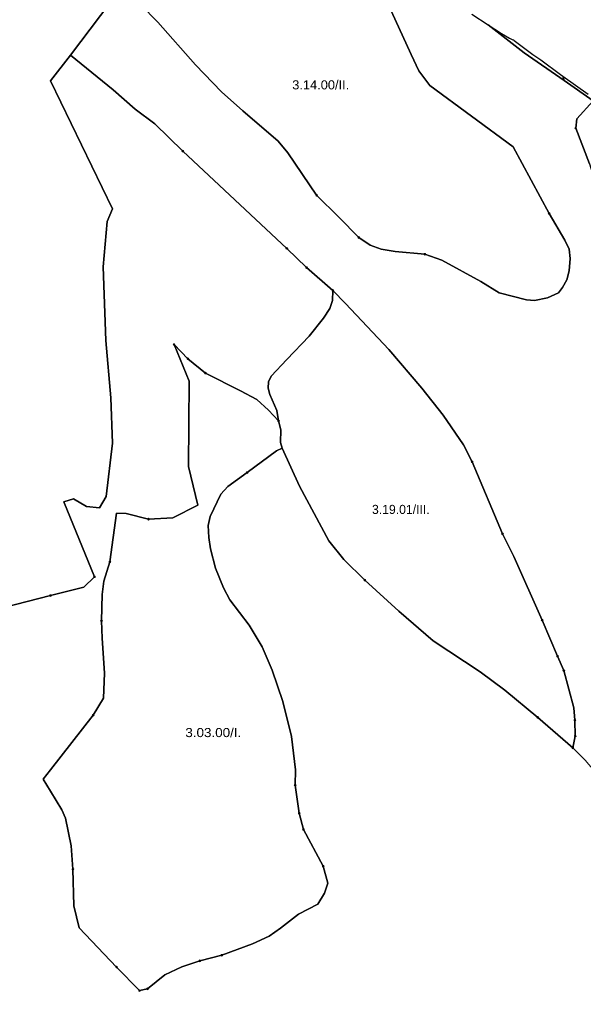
# Model space of a CAD drawing. Extents: x -650455 to -642254, y -1075222 to -1066610.
# Drawn here: x -645034 to -644416, y -1073102 to -1072036 of the extents above; entities that cross this region are included whole.
import ezdxf
from ezdxf.enums import TextEntityAlignment as Align

# ---------------------------------------------------------------- set-up
doc = ezdxf.new("R2010")
doc.units = 0
doc.header["$LTSCALE"] = 4
doc.header["$PDMODE"] = 32
doc.header["$PDSIZE"] = 2
for name, color, linetype, lineweight in [('1', 7, 'Continuous', 25), ('11', 7, 'Continuous', 13), ('12', 7, 'Continuous', 13), ('13', 7, 'Continuous', 13), ('14', 7, 'Continuous', 13)]:
    doc.layers.add(name, color=color, linetype=linetype, lineweight=lineweight)
doc.layers.add('2', color=7, linetype='Continuous')

msp = doc.modelspace()

# ---------------------------------------------------------------- linework, layer by layer
at = {"layer": '1'}
for points in [[(-644841.196, -1072085.989), (-644882.287, -1072039.303), (-644920.668, -1072000), (-644846.005, -1071899.418), (-644841.808, -1071890.5), (-644840.584, -1071879.659), (-644841.109, -1071869.867), (-644842.508, -1071858.851), (-644848.802, -1071841.89), (-644852.999, -1071832.972), (-644858.507, -1071824.054), (-644814.968, -1071847.135), (-644781.395, -1071868.992)], [(-644431.857, -1072311.904), (-644430.633, -1072298.615), (-644431.682, -1072288.473), (-644436.403, -1072278.331), (-644453.627, -1072249.305), (-644492.882, -1072176.04), (-644584.42, -1072108.721), (-644596.572, -1072092.634), (-644604.965, -1072074.973), (-644630.931, -1072017.97), (-644644.606, -1072000), (-644652.089, -1071990.168), (-644682.776, -1071960.792), (-644705.508, -1071942.607), (-644747.386, -1071912.357), (-644761.374, -1071900.641), (-644769.942, -1071891.374), (-644776.237, -1071882.107), (-644781.395, -1071868.992), (-644763.822, -1071881.057), (-644761.199, -1071879.659), (-644742.849, -1071890.721)], [(-644923.589, -1072003.101), (-644978.202, -1072075.468), (-645000, -1072103.795), (-644932.308, -1072244.028), (-644938, -1072258.001), (-644942.5, -1072307.5), (-644939.5, -1072388.5), (-644934, -1072451.501)], [(-644504.788, -1072600.507), (-644538.098, -1072521.472), (-644547.541, -1072502.937), (-644569.835, -1072470.239), (-644593.265, -1072440.689), (-644629.198, -1072398.199), (-644676.672, -1072348.015), (-644690.563, -1072333.557), (-644719.414, -1072308.552), (-644741.009, -1072287.394), (-644855.103, -1072180.732), (-644885.79, -1072150.832), (-644907.123, -1072134.745), (-644931.428, -1072113.412), (-644978.202, -1072075.468), (-644923.589, -1072003.101)], [(-644920.668, -1072000), (-644882.287, -1072039.303), (-644841.196, -1072085.989), (-644812.607, -1072115.89), (-644789.351, -1072136.698), (-644750.62, -1072169.92), (-644740.129, -1072182.51), (-644708.393, -1072229.022), (-644684.088, -1072253.327), (-644662.318, -1072275.534), (-644649.728, -1072283.927), (-644637.838, -1072288.298), (-644622.451, -1072290.921), (-644589.753, -1072293.893), (-644571.218, -1072300.538), (-644528.64, -1072323.619), (-644508.357, -1072336.209), (-644478.457, -1072343.902), (-644469.539, -1072344.602), (-644455.463, -1072341.629), (-644443.223, -1072336.034), (-644439.026, -1072330.264), (-644434.305, -1072322.045), (-644431.857, -1072311.904)], [(-644630.931, -1072017.97), (-644604.965, -1072074.973), (-644596.572, -1072092.634), (-644584.42, -1072108.721), (-644492.882, -1072176.04), (-644453.627, -1072249.305), (-644436.403, -1072278.331), (-644431.682, -1072288.473), (-644430.633, -1072298.615), (-644431.857, -1072311.904), (-644434.305, -1072322.045), (-644439.026, -1072330.264), (-644443.223, -1072336.034), (-644455.463, -1072341.629), (-644469.539, -1072344.602), (-644478.457, -1072343.902), (-644508.357, -1072336.209), (-644528.64, -1072323.619), (-644571.218, -1072300.538), (-644589.753, -1072293.893), (-644622.451, -1072290.921), (-644637.838, -1072288.298), (-644649.728, -1072283.927), (-644662.318, -1072275.534), (-644684.088, -1072253.327), (-644708.393, -1072229.022), (-644740.129, -1072182.51), (-644750.62, -1072169.92), (-644789.351, -1072136.698), (-644812.607, -1072115.89), (-644841.196, -1072085.989)], [(-644538.207, -1072030.496), (-644520.385, -1072042.196), (-644480.817, -1072072.875), (-644437.149, -1072103.18), (-644405.404, -1072125.733), (-644423.152, -1072145.492), (-644424.551, -1072155.634), (-644409.426, -1072194.802), (-644395.962, -1072238.516), (-644382.411, -1072266.143), (-644377.69, -1072283.279), (-644368.51, -1072344.479), (-644363.526, -1072367.91), (-644357.056, -1072388.717), (-644349.887, -1072398.859), (-644340.095, -1072405.329), (-644329.079, -1072409.525), (-644322.085, -1072408.476), (-644311.769, -1072403.231), (-644304.425, -1072396.061), (-644301.277, -1072389.242), (-644299.529, -1072379.975), (-644298.392, -1072369.308), (-644286.239, -1072437.852)], [(-645051.292, -1072681.171), (-645000, -1072668.218), (-644963.5, -1072659), (-644952, -1072647.5), (-644985.633, -1072565.416), (-644974.792, -1072562.094), (-644960.629, -1072570.487), (-644946.5, -1072572.001), (-644939, -1072559.5), (-644932, -1072501.001), (-644934, -1072451.501), (-644939.5, -1072388.5), (-644942.5, -1072307.5), (-644938, -1072258.001), (-644932.308, -1072244.028), (-645000, -1072103.795), (-644978.202, -1072075.468), (-644931.428, -1072113.412), (-644907.123, -1072134.745), (-644885.79, -1072150.832), (-644855.103, -1072180.732), (-644741.009, -1072287.394), (-644719.414, -1072308.552), (-644690.563, -1072333.557)], [(-644405.404, -1072125.733), (-644437.149, -1072103.18), (-644438.697, -1072098.552), (-644410.923, -1072118.41)], [(-644409.426, -1072194.802), (-644424.551, -1072155.634), (-644423.152, -1072145.492), (-644405.404, -1072125.733)], [(-644690.563, -1072333.557), (-644690.913, -1072344.747), (-644693.885, -1072353.49), (-644700.967, -1072363.982), (-644716.704, -1072383.566), (-644741.009, -1072409.444), (-644758.407, -1072427.629), (-644761.03, -1072433.924), (-644761.555, -1072440.569), (-644759.806, -1072447.563), (-644752.2, -1072465.224), (-644750.102, -1072476.589), (-644761.118, -1072464.699), (-644773.882, -1072453.158), (-644791.892, -1072443.716), (-644830.186, -1072424.132), (-644849.42, -1072408.395), (-644864.72, -1072393.008), (-644848.109, -1072433.225), (-644848.721, -1072526.773), (-644838.492, -1072569.088), (-644866.119, -1072582.902), (-644892.522, -1072584.476), (-644917.177, -1072578.356), (-644927.668, -1072577.656), (-644934.935, -1072631.107), (-644941.579, -1072652.265), (-644943.59, -1072666.953), (-644944.115, -1072695.979), (-644943.415, -1072715.038), (-644941.055, -1072753.157), (-644941.841, -1072780.784), (-644953.207, -1072799.494), (-645000, -1072859.198), (-645008.025, -1072869.436), (-645000, -1072882.662), (-644987.654, -1072903.009), (-644983.807, -1072912.451), (-644977.337, -1072942.526), (-644975.501, -1072968.405)], [(-644968.595, -1073032.752), (-644974.54, -1073008.447), (-644975.501, -1072968.405), (-644977.337, -1072942.526), (-644983.807, -1072912.451), (-644987.654, -1072903.009), (-645000, -1072882.662), (-645008.025, -1072869.436), (-645000, -1072859.198), (-644953.207, -1072799.494), (-644941.841, -1072780.784), (-644941.055, -1072753.157), (-644943.415, -1072715.038), (-644944.115, -1072695.979), (-644943.59, -1072666.953), (-644941.579, -1072652.265), (-644934.935, -1072631.107), (-644927.668, -1072577.656), (-644917.177, -1072578.356), (-644892.522, -1072584.476), (-644866.119, -1072582.902), (-644838.492, -1072569.088), (-644848.721, -1072526.773), (-644848.109, -1072433.225), (-644864.72, -1072393.008), (-644849.42, -1072408.395), (-644830.186, -1072424.132), (-644791.892, -1072443.716), (-644773.882, -1072453.158), (-644761.118, -1072464.699), (-644750.102, -1072476.589)], [(-644934, -1072451.501), (-644932, -1072501.001), (-644939, -1072559.5), (-644946.5, -1072572.001), (-644960.629, -1072570.487), (-644974.792, -1072562.094), (-644985.633, -1072565.416), (-644952, -1072647.5), (-644963.5, -1072659), (-645000, -1072668.218), (-645051.292, -1072681.171)], [(-644750.102, -1072476.589), (-644747.829, -1072486.556), (-644748.004, -1072500.37), (-644746.255, -1072506.665), (-644752.385, -1072509.582), (-644784.471, -1072533.362), (-644805.629, -1072548.4), (-644813.322, -1072556.968), (-644825.037, -1072581.623), (-644827.136, -1072591.24), (-644826.699, -1072604.529), (-644824.775, -1072616.769), (-644819.18, -1072638.101), (-644810.35, -1072659.609), (-644803.53, -1072672.723), (-644782.198, -1072700.525), (-644768.122, -1072724.481), (-644757.106, -1072750.184), (-644745.478, -1072784.281), (-644736.036, -1072822.925), (-644731.752, -1072859.47), (-644731.926, -1072876.256), (-644727.468, -1072906.856), (-644722.921, -1072924.866), (-644701.152, -1072965.083), (-644696.256, -1072983.443), (-644699.753, -1072994.634), (-644707.097, -1073006.699), (-644728.342, -1073017.54), (-644747.926, -1073033.102), (-644760.341, -1073041.67), (-644778.7, -1073050.063), (-644812.273, -1073062.653), (-644836.491, -1073068.773), (-644856.074, -1073075.417), (-644874.609, -1073083.985), (-644893.669, -1073099.547), (-644902.412, -1073101.471), (-644927.591, -1073075.592), (-644968.595, -1073032.752)], [(-644975.501, -1072968.405), (-644974.54, -1073008.447), (-644968.595, -1073032.752), (-644927.591, -1073075.592), (-644902.412, -1073101.471), (-644893.669, -1073099.547), (-644874.609, -1073083.985), (-644856.074, -1073075.417), (-644836.491, -1073068.773), (-644812.273, -1073062.653), (-644778.7, -1073050.063), (-644760.341, -1073041.67), (-644747.926, -1073033.102), (-644728.342, -1073017.54), (-644707.097, -1073006.699), (-644699.753, -1072994.634), (-644696.256, -1072983.443), (-644701.152, -1072965.083), (-644722.921, -1072924.866), (-644727.468, -1072906.856), (-644731.926, -1072876.256), (-644731.752, -1072859.47), (-644736.036, -1072822.925), (-644745.478, -1072784.281), (-644757.106, -1072750.184), (-644768.122, -1072724.481), (-644782.198, -1072700.525), (-644803.53, -1072672.723), (-644810.35, -1072659.609), (-644819.18, -1072638.101), (-644824.775, -1072616.769), (-644826.699, -1072604.529), (-644827.136, -1072591.24), (-644825.037, -1072581.623), (-644813.322, -1072556.968), (-644805.629, -1072548.4), (-644784.471, -1072533.362), (-644752.385, -1072509.582), (-644746.255, -1072506.665), (-644727.03, -1072548.225)], [(-644727.03, -1072548.225), (-644695.119, -1072608.201), (-644678.508, -1072628.484), (-644655.514, -1072651.216), (-644618.27, -1072685.138), (-644580.763, -1072717.661), (-644529.268, -1072751.758), (-644502.165, -1072771.867), (-644465.97, -1072801.767), (-644427.764, -1072835.165), (-644413.997, -1072848.687)], [(-644413.997, -1072848.687), (-644427.764, -1072835.165), (-644424.966, -1072822.225), (-644425.316, -1072804.914), (-644426.54, -1072791.45), (-644437.556, -1072750.534), (-644444.375, -1072734.797), (-644461.249, -1072695.105), (-644492.286, -1072625.512), (-644504.788, -1072600.507)]]:
    msp.add_lwpolyline(points, dxfattribs=at)
for points in [[(-644438.697, -1072098.552), (-644437.149, -1072103.18), (-644480.817, -1072072.875), (-644520.385, -1072042.196), (-644505.751, -1072051.804), (-644497.002, -1072057.025), (-644493.333, -1072058.718), (-644492.204, -1072058.859), (-644491.922, -1072059.566), (-644471.32, -1072074.806), (-644462.853, -1072080.592), (-644441.121, -1072096.818)], [(-644427.764, -1072835.165), (-644465.97, -1072801.767), (-644502.165, -1072771.867), (-644529.268, -1072751.758), (-644580.763, -1072717.661), (-644618.27, -1072685.138), (-644655.514, -1072651.216), (-644678.508, -1072628.484), (-644695.119, -1072608.201), (-644727.03, -1072548.225), (-644746.255, -1072506.665), (-644748.004, -1072500.37), (-644747.829, -1072486.556), (-644750.102, -1072476.589), (-644752.2, -1072465.224), (-644759.806, -1072447.563), (-644761.555, -1072440.569), (-644761.03, -1072433.924), (-644758.407, -1072427.629), (-644741.009, -1072409.444), (-644716.704, -1072383.566), (-644700.967, -1072363.982), (-644693.885, -1072353.49), (-644690.913, -1072344.747), (-644690.563, -1072333.557), (-644676.672, -1072348.015), (-644629.198, -1072398.199), (-644593.265, -1072440.689), (-644569.835, -1072470.239), (-644547.541, -1072502.937), (-644538.098, -1072521.472), (-644504.788, -1072600.507), (-644492.286, -1072625.512), (-644461.249, -1072695.105), (-644444.375, -1072734.797), (-644437.556, -1072750.534), (-644426.54, -1072791.45), (-644425.316, -1072804.914), (-644424.966, -1072822.225)]]:
    msp.add_lwpolyline(points, close=True, dxfattribs=at)
at = {"layer": '11'}
for p, q in [((-644727.468, -1072906.856), (-644731.926, -1072876.256)), ((-644722.921, -1072924.866), (-644727.468, -1072906.856)), ((-644968.595, -1073032.752), (-644927.591, -1073075.592)), ((-644927.591, -1073075.592), (-644902.412, -1073101.471))]:
    msp.add_line(p, q, dxfattribs=at)
for points in [[(-645000, -1072668.218), (-644963.5, -1072659), (-644952, -1072647.5), (-644985.633, -1072565.416), (-644974.792, -1072562.094), (-644960.629, -1072570.487), (-644946.5, -1072572.001), (-644939, -1072559.5), (-644932, -1072501.001), (-644934, -1072451.501), (-644939.5, -1072388.5), (-644942.5, -1072307.5), (-644938, -1072258.001), (-644932.308, -1072244.028), (-645000, -1072103.795), (-644978.202, -1072075.468), (-644923.589, -1072003.101), (-644924, -1072000)], [(-644410.923, -1072118.41), (-644438.697, -1072098.552), (-644437.149, -1072103.18), (-644405.404, -1072125.733)], [(-645232, -1072393.5), (-645239, -1072447.501), (-645252.5, -1072519.501), (-645249.5, -1072546.5), (-645229.5, -1072578), (-645192.5, -1072623), (-645125, -1072686.501), (-645107.317, -1072702.887), (-645051.292, -1072681.171), (-645000, -1072668.218)], [(-644864.72, -1072393.008), (-644848.109, -1072433.225), (-644848.721, -1072526.773), (-644838.492, -1072569.088), (-644866.119, -1072582.902), (-644892.522, -1072584.476), (-644917.177, -1072578.356), (-644927.668, -1072577.656), (-644934.935, -1072631.107), (-644941.579, -1072652.265), (-644943.59, -1072666.953), (-644944.115, -1072695.979), (-644943.415, -1072715.038), (-644941.055, -1072753.157), (-644941.841, -1072780.784), (-644953.207, -1072799.494), (-645000, -1072859.198), (-645008.025, -1072869.436), (-645000, -1072882.662), (-644987.654, -1072903.009), (-644983.807, -1072912.451), (-644977.337, -1072942.526), (-644975.501, -1072968.405), (-644974.54, -1073008.447), (-644968.595, -1073032.752)], [(-644731.926, -1072876.256), (-644731.752, -1072859.47), (-644736.036, -1072822.925), (-644745.478, -1072784.281), (-644757.106, -1072750.184), (-644768.122, -1072724.481), (-644782.198, -1072700.525), (-644803.53, -1072672.723), (-644810.35, -1072659.609), (-644819.18, -1072638.101), (-644824.775, -1072616.769), (-644826.699, -1072604.529), (-644827.136, -1072591.24), (-644825.037, -1072581.623), (-644813.322, -1072556.968), (-644805.629, -1072548.4), (-644784.471, -1072533.362), (-644752.385, -1072509.582), (-644746.255, -1072506.665), (-644748.004, -1072500.37), (-644747.829, -1072486.556), (-644750.102, -1072476.589), (-644761.118, -1072464.699), (-644773.882, -1072453.158), (-644791.892, -1072443.716), (-644830.186, -1072424.132), (-644849.42, -1072408.395), (-644864.72, -1072393.008)], [(-644812.273, -1073062.653), (-644778.7, -1073050.063), (-644760.341, -1073041.67), (-644747.926, -1073033.102), (-644728.342, -1073017.54), (-644707.097, -1073006.699), (-644699.753, -1072994.634), (-644696.256, -1072983.443), (-644701.152, -1072965.083), (-644722.921, -1072924.866)], [(-644902.412, -1073101.471), (-644893.669, -1073099.547), (-644874.609, -1073083.985), (-644856.074, -1073075.417), (-644836.491, -1073068.773), (-644812.273, -1073062.653)]]:
    msp.add_lwpolyline(points, dxfattribs=at)
for p in [(-644864.72, -1072393.008), (-645000, -1072668.218), (-644731.926, -1072876.256), (-644727.468, -1072906.856), (-644722.921, -1072924.866), (-644812.273, -1073062.653), (-644927.591, -1073075.592), (-644902.412, -1073101.471)]:
    msp.add_point(p, dxfattribs=at)
at = {"layer": '12'}
for p, q in [((-644741.009, -1072287.394), (-644855.103, -1072180.732)), ((-644849.42, -1072408.395), (-644830.186, -1072424.132)), ((-644427.764, -1072835.165), (-644465.97, -1072801.767))]:
    msp.add_line(p, q, dxfattribs=at)
for points in [[(-644920.668, -1072000), (-644882.287, -1072039.303), (-644841.196, -1072085.989), (-644812.607, -1072115.89), (-644789.351, -1072136.698), (-644750.62, -1072169.92), (-644740.129, -1072182.51), (-644708.393, -1072229.022)], [(-644453.627, -1072249.305), (-644492.882, -1072176.04), (-644584.42, -1072108.721), (-644596.572, -1072092.634), (-644604.965, -1072074.973), (-644630.931, -1072017.97)], [(-644855.103, -1072180.732), (-644885.79, -1072150.832), (-644907.123, -1072134.745), (-644931.428, -1072113.412), (-644978.202, -1072075.468), (-645000, -1072103.795), (-644932.308, -1072244.028), (-644938, -1072258.001), (-644942.5, -1072307.5), (-644939.5, -1072388.5), (-644934, -1072451.501), (-644932, -1072501.001), (-644939, -1072559.5), (-644946.5, -1072572.001), (-644960.629, -1072570.487), (-644974.792, -1072562.094), (-644985.633, -1072565.416), (-644952, -1072647.5)], [(-644708.393, -1072229.022), (-644684.088, -1072253.327), (-644662.318, -1072275.534), (-644649.728, -1072283.927), (-644637.838, -1072288.298), (-644622.451, -1072290.921), (-644589.753, -1072293.893)], [(-644589.753, -1072293.893), (-644571.218, -1072300.538), (-644528.64, -1072323.619), (-644508.357, -1072336.209), (-644478.457, -1072343.902), (-644469.539, -1072344.602), (-644455.463, -1072341.629), (-644443.223, -1072336.034), (-644439.026, -1072330.264), (-644434.305, -1072322.045), (-644431.857, -1072311.904), (-644430.633, -1072298.615), (-644431.682, -1072288.473), (-644436.403, -1072278.331), (-644453.627, -1072249.305)], [(-644690.563, -1072333.557), (-644719.414, -1072308.552), (-644741.009, -1072287.394)], [(-644750.102, -1072476.589), (-644752.2, -1072465.224), (-644759.806, -1072447.563), (-644761.555, -1072440.569), (-644761.03, -1072433.924), (-644758.407, -1072427.629), (-644741.009, -1072409.444), (-644716.704, -1072383.566), (-644700.967, -1072363.982), (-644693.885, -1072353.49), (-644690.913, -1072344.747), (-644690.563, -1072333.557)], [(-644892.522, -1072584.476), (-644866.119, -1072582.902), (-644838.492, -1072569.088), (-644848.721, -1072526.773), (-644848.109, -1072433.225), (-644864.72, -1072393.008), (-644849.42, -1072408.395)], [(-644830.186, -1072424.132), (-644791.892, -1072443.716), (-644773.882, -1072453.158), (-644761.118, -1072464.699), (-644750.102, -1072476.589)], [(-644655.514, -1072651.216), (-644678.508, -1072628.484), (-644695.119, -1072608.201), (-644727.03, -1072548.225), (-644746.255, -1072506.665), (-644752.385, -1072509.582), (-644784.471, -1072533.362)], [(-644784.471, -1072533.362), (-644805.629, -1072548.4), (-644813.322, -1072556.968), (-644825.037, -1072581.623), (-644827.136, -1072591.24), (-644826.699, -1072604.529), (-644824.775, -1072616.769), (-644819.18, -1072638.101), (-644810.35, -1072659.609), (-644803.53, -1072672.723), (-644782.198, -1072700.525), (-644768.122, -1072724.481), (-644757.106, -1072750.184), (-644745.478, -1072784.281), (-644736.036, -1072822.925), (-644731.752, -1072859.47), (-644731.926, -1072876.256)], [(-644934.935, -1072631.107), (-644927.668, -1072577.656), (-644917.177, -1072578.356), (-644892.522, -1072584.476)], [(-644944.115, -1072695.979), (-644943.59, -1072666.953), (-644941.579, -1072652.265), (-644934.935, -1072631.107)], [(-644952, -1072647.5), (-644963.5, -1072659), (-645000, -1072668.218), (-645051.292, -1072681.171)], [(-644465.97, -1072801.767), (-644502.165, -1072771.867), (-644529.268, -1072751.758), (-644580.763, -1072717.661), (-644618.27, -1072685.138), (-644655.514, -1072651.216)], [(-644953.207, -1072799.494), (-644941.841, -1072780.784), (-644941.055, -1072753.157), (-644943.415, -1072715.038), (-644944.115, -1072695.979)], [(-644975.501, -1072968.405), (-644977.337, -1072942.526), (-644983.807, -1072912.451), (-644987.654, -1072903.009), (-645000, -1072882.662), (-645008.025, -1072869.436), (-645000, -1072859.198), (-644953.207, -1072799.494)], [(-644332.951, -1072950.978), (-644384.621, -1072887.855), (-644400.183, -1072865.124), (-644413.997, -1072848.687), (-644427.764, -1072835.165)], [(-644731.926, -1072876.256), (-644727.468, -1072906.856), (-644722.921, -1072924.866), (-644701.152, -1072965.083)], [(-644893.669, -1073099.547), (-644902.412, -1073101.471), (-644927.591, -1073075.592), (-644968.595, -1073032.752), (-644974.54, -1073008.447), (-644975.501, -1072968.405)], [(-644701.152, -1072965.083), (-644696.256, -1072983.443), (-644699.753, -1072994.634), (-644707.097, -1073006.699), (-644728.342, -1073017.54), (-644747.926, -1073033.102), (-644760.341, -1073041.67), (-644778.7, -1073050.063), (-644812.273, -1073062.653), (-644836.491, -1073068.773)], [(-644836.491, -1073068.773), (-644856.074, -1073075.417), (-644874.609, -1073083.985), (-644893.669, -1073099.547)]]:
    msp.add_lwpolyline(points, dxfattribs=at)
for p in [(-644855.103, -1072180.732), (-644708.393, -1072229.022), (-644453.627, -1072249.305), (-644741.009, -1072287.394), (-644589.753, -1072293.893), (-644690.563, -1072333.557), (-644849.42, -1072408.395), (-644830.186, -1072424.132), (-644750.102, -1072476.589), (-644784.471, -1072533.362), (-644892.522, -1072584.476), (-644934.935, -1072631.107), (-644952, -1072647.5), (-644655.514, -1072651.216), (-644944.115, -1072695.979), (-644953.207, -1072799.494), (-644465.97, -1072801.767), (-644427.764, -1072835.165), (-644731.926, -1072876.256), (-644975.501, -1072968.405), (-644701.152, -1072965.083), (-644836.491, -1073068.773), (-644893.669, -1073099.547)]:
    msp.add_point(p, dxfattribs=at)
at = {"layer": '13'}
msp.add_line((-644444.375, -1072734.797), (-644437.556, -1072750.534), dxfattribs=at)
for points in [[(-644662.318, -1072275.534), (-644684.088, -1072253.327), (-644708.393, -1072229.022), (-644740.129, -1072182.51), (-644750.62, -1072169.92), (-644789.351, -1072136.698), (-644812.607, -1072115.89), (-644841.196, -1072085.989), (-644882.287, -1072039.303), (-644920.668, -1072000), (-644923.589, -1072003.101), (-644978.202, -1072075.468), (-644931.428, -1072113.412), (-644907.123, -1072134.745), (-644885.79, -1072150.832), (-644855.103, -1072180.732), (-644741.009, -1072287.394), (-644719.414, -1072308.552)], [(-644630.931, -1072017.97), (-644604.965, -1072074.973), (-644596.572, -1072092.634), (-644584.42, -1072108.721), (-644492.882, -1072176.04), (-644453.627, -1072249.305)], [(-644424.551, -1072155.634), (-644423.152, -1072145.492), (-644405.404, -1072125.733), (-644437.149, -1072103.18), (-644480.817, -1072072.875), (-644520.385, -1072042.196), (-644538.207, -1072030.496)], [(-644409.426, -1072194.802), (-644424.551, -1072155.634)], [(-644453.627, -1072249.305), (-644436.403, -1072278.331), (-644431.682, -1072288.473), (-644430.633, -1072298.615), (-644431.857, -1072311.904), (-644434.305, -1072322.045), (-644439.026, -1072330.264), (-644443.223, -1072336.034), (-644455.463, -1072341.629), (-644469.539, -1072344.602), (-644478.457, -1072343.902), (-644508.357, -1072336.209), (-644528.64, -1072323.619), (-644571.218, -1072300.538), (-644589.753, -1072293.893), (-644622.451, -1072290.921), (-644637.838, -1072288.298), (-644649.728, -1072283.927), (-644662.318, -1072275.534)], [(-644719.414, -1072308.552), (-644690.563, -1072333.557), (-644676.672, -1072348.015), (-644629.198, -1072398.199), (-644593.265, -1072440.689), (-644569.835, -1072470.239), (-644547.541, -1072502.937), (-644538.098, -1072521.472)], [(-644504.788, -1072600.507), (-644538.098, -1072521.472), (-644547.541, -1072502.937), (-644569.835, -1072470.239), (-644593.265, -1072440.689), (-644629.198, -1072398.199), (-644676.672, -1072348.015), (-644690.563, -1072333.557), (-644690.913, -1072344.747), (-644693.885, -1072353.49), (-644700.967, -1072363.982), (-644716.704, -1072383.566), (-644741.009, -1072409.444), (-644758.407, -1072427.629), (-644761.03, -1072433.924), (-644761.555, -1072440.569), (-644759.806, -1072447.563), (-644752.2, -1072465.224), (-644750.102, -1072476.589), (-644747.829, -1072486.556), (-644748.004, -1072500.37), (-644746.255, -1072506.665), (-644727.03, -1072548.225), (-644695.119, -1072608.201), (-644678.508, -1072628.484), (-644655.514, -1072651.216)], [(-644538.098, -1072521.472), (-644504.788, -1072600.507), (-644492.286, -1072625.512), (-644461.249, -1072695.105), (-644444.375, -1072734.797)], [(-644461.249, -1072695.105), (-644492.286, -1072625.512), (-644504.788, -1072600.507)], [(-644655.514, -1072651.216), (-644618.27, -1072685.138), (-644580.763, -1072717.661), (-644529.268, -1072751.758), (-644502.165, -1072771.867), (-644465.97, -1072801.767), (-644427.764, -1072835.165), (-644424.966, -1072822.225), (-644425.316, -1072804.914)], [(-644425.316, -1072804.914), (-644426.54, -1072791.45), (-644437.556, -1072750.534), (-644444.375, -1072734.797), (-644461.249, -1072695.105)], [(-644437.556, -1072750.534), (-644426.54, -1072791.45), (-644425.316, -1072804.914), (-644424.966, -1072822.225)], [(-644424.966, -1072822.225), (-644427.764, -1072835.165), (-644413.997, -1072848.687)]]:
    msp.add_lwpolyline(points, dxfattribs=at)
for p in [(-644424.551, -1072155.634), (-644662.318, -1072275.534), (-644719.414, -1072308.552), (-644538.098, -1072521.472), (-644504.788, -1072600.507), (-644461.249, -1072695.105), (-644444.375, -1072734.797), (-644437.556, -1072750.534), (-644425.316, -1072804.914), (-644424.966, -1072822.225)]:
    msp.add_point(p, dxfattribs=at)
at = {"layer": '14'}
msp.add_lwpolyline([(-644405.404, -1072125.733), (-644423.152, -1072145.492), (-644424.551, -1072155.634), (-644409.426, -1072194.802)], dxfattribs=at)

# ---------------------------------------------------------------- texts
at = {"layer": '2'}
for s, width, p in [('3.14.00/II.', 1.05, (-644703.938, -1072113.086)), ('3.03.00/I.', 1.1, (-644821.649, -1072823.414))]:
    msp.add_text(s, height=10, dxfattribs=dict(at, width=width)).set_placement(p, align=Align.CENTER)
msp.add_text('3.19.01/III.', height=10, dxfattribs=at).set_placement((-644616.149, -1072578.713), align=Align.CENTER)

doc.saveas('drawing.dxf')
